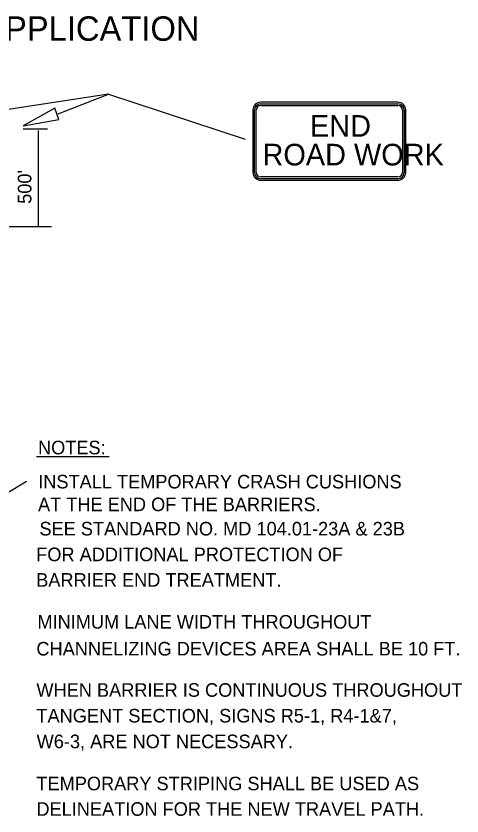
# Model space of a CAD drawing. Extents: x 1531.42 to 1538.58, y 1529.59 to 1539.57.
# Drawn here: x 1535.649 to 1537.619, y 1536.04 to 1539.575 of the extents above; entities that cross this region are included whole.
import ezdxf

# ---------------------------------------------------------------- set-up
doc = ezdxf.new("R2010")
doc.units = 0
for name, color, linetype in [('DETL-DIMS', 7, 'Continuous'), ('DETL-LINE', 7, 'Continuous'), ('DETL-NOTE', 7, 'Continuous'), ('DETL-TITL', 7, 'Continuous')]:
    doc.layers.add(name, color=color, linetype=linetype)

msp = doc.modelspace()

# ---------------------------------------------------------------- linework, layer by layer
at = {"layer": 'DETL-DIMS'}
for p, q in [((1536.0584, 1539.2298), (1535.359, 1539.1223)), ((1535.8355, 1539.1426), (1536.0584, 1539.2298)), ((1536.0584, 1539.2298), (1536.6608, 1539.0307)), ((1535.6814, 1539.0757), (1535.7888, 1539.0757)), ((1535.7483, 1538.6449), (1535.7483, 1539.0686)), ((1535.5651, 1538.6449), (1535.8056, 1538.6449)), ((1534.9864, 1537.0877), (1535.6964, 1537.5201))]:
    msp.add_line(p, q, dxfattribs=at)
msp.add_lwpolyline([(1535.839, 1539.1179), (1535.8205, 1539.1681), (1535.6805, 1539.0897)], close=True, dxfattribs=at)
at = {"layer": 'DETL-LINE'}
for p, q in [((1537.336, 1539.1934), (1536.7299, 1539.1934)), ((1536.7299, 1539.1864), (1537.336, 1539.1864)), ((1536.7299, 1539.1791), (1537.336, 1539.1791)), ((1536.6956, 1539.1591), (1536.6956, 1538.8835)), ((1536.7026, 1538.8835), (1536.7026, 1539.1591)), ((1536.7099, 1538.8835), (1536.7099, 1539.1591)), ((1537.3557, 1539.1591), (1537.3557, 1538.8835)), ((1537.3558, 1539.1589), (1537.3557, 1539.1591)), ((1537.3637, 1539.1591), (1537.3637, 1538.8835)), ((1537.3707, 1538.8835), (1537.3707, 1539.1591)), ((1537.336, 1538.8638), (1536.7299, 1538.8638)), ((1537.336, 1538.8559), (1536.7299, 1538.8559)), ((1536.7299, 1538.8489), (1537.336, 1538.8489))]:
    msp.add_line(p, q, dxfattribs=at)
for centre, radius, start, end in [((1536.73, 1539.1589), 0.0345, 90, 180), ((1536.73, 1539.1589), 0.0276, 90, 180), ((1536.73, 1539.1589), 0.0198, 90, 180), ((1537.336, 1539.1589), 0.0345, 0, 90), ((1537.336, 1539.1589), 0.0276, 0, 90), ((1537.336, 1539.1589), 0.0198, 0, 90), ((1536.73, 1538.8835), 0.0345, 180, 270), ((1536.73, 1538.8835), 0.0276, 180, 270), ((1536.73, 1538.8835), 0.0198, 180, 270), ((1537.336, 1538.8835), 0.0345, 270, 0), ((1537.336, 1538.8835), 0.0198, 270, 0), ((1537.336, 1538.8835), 0.0276, 270, 0)]:
    msp.add_arc(centre, radius, start, end, dxfattribs=at)
at = {"layer": 'DETL-NOTE'}
msp.add_line((1535.7399, 1537.6293), (1536.0607, 1537.6293), dxfattribs=at)

# ---------------------------------------------------------------- texts
at = {"layer": 'DETL-LINE'}
for s, p in [('END', (1536.9476, 1539.0414)), ('ROAD WORK', (1536.7378, 1538.9146))]:
    msp.add_text(s, height=0.09541, rotation=360, dxfattribs=at).set_placement(p)
at = {"layer": 'DETL-NOTE'}
msp.add_text("500'", height=0.06, rotation=90, dxfattribs=at).set_placement((1535.7174, 1538.7449))
for s, p in [('NOTES:', (1535.7466, 1537.6382)), ('INSTALL TEMPORARY CRASH CUSHIONS', (1535.7474, 1537.4875)), ('AT THE END OF THE BARRIERS.', (1535.7466, 1537.3871)), ('SEE STANDARD NO. MD 104.01-23A & 23B', (1535.7527, 1537.2797)), ('FOR ADDITIONAL PROTECTION OF', (1535.7386, 1537.1661)), ('BARRIER END TREATMENT.', (1535.7386, 1537.0533)), ('MINIMUM LANE WIDTH THROUGHOUT ', (1535.7439, 1536.8683)), ('CHANNELIZING DEVICES AREA SHALL BE 10 FT.', (1535.7395, 1536.7495)), ('WHEN BARRIER IS CONTINUOUS THROUGHOUT', (1535.7395, 1536.5671)), ('TANGENT SECTION, SIGNS R5-1, R4-1&7,', (1535.7395, 1536.4535)), ('W6-3, ARE NOT NECESSARY.', (1535.7404, 1536.3399)), ('TEMPORARY STRIPING SHALL BE USED AS', (1535.7395, 1536.154)), ('DELINEATION FOR THE NEW TRAVEL PATH.', (1535.7395, 1536.0413))]:
    msp.add_text(s, height=0.06, dxfattribs=at).set_placement(p)
at = {"layer": 'DETL-TITL'}
msp.add_text('TEMPORARY TRAFFIC CONTROL TYPICAL APPLICATION', height=0.108, dxfattribs=at).set_placement((1532.5115, 1539.465))

doc.saveas('drawing.dxf')
